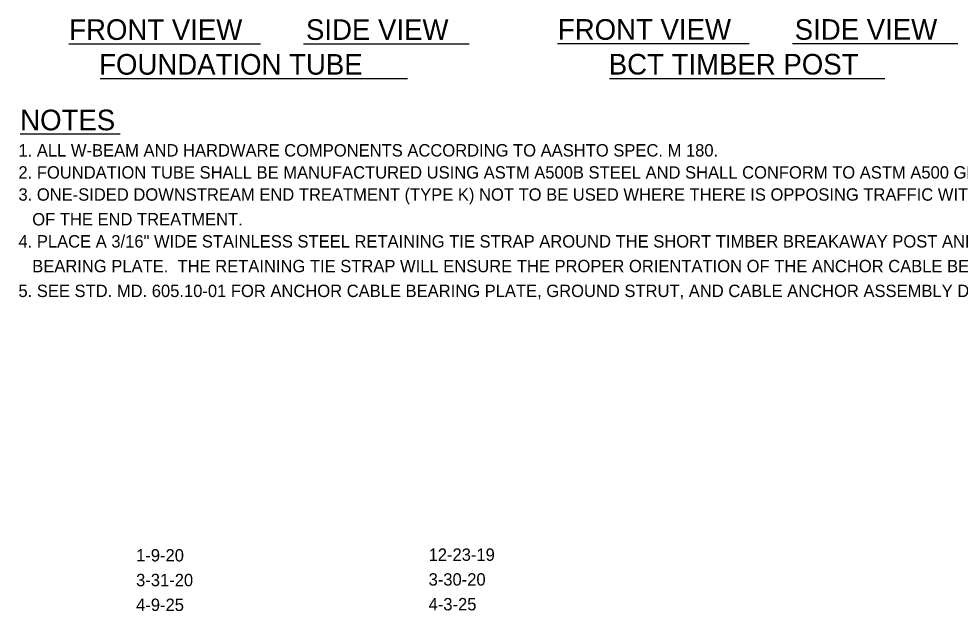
# Model space of a CAD drawing. Extents: x 12.2 to 54.5, y -7.8 to 16.1.
# Drawn here: x 12.398 to 16.963, y 6.013 to 8.884 of the extents above; entities that cross this region are included whole.
import ezdxf

# ---------------------------------------------------------------- set-up
doc = ezdxf.new("R2010")
doc.units = 0
for name, color, linetype in [('DETL-NOTE', 7, 'Continuous'), ('DETL-TITL', 7, 'Continuous'), ('TTLB-TEXT', 7, 'Continuous')]:
    doc.layers.add(name, color=color, linetype=linetype)

msp = doc.modelspace()

# ---------------------------------------------------------------- linework, layer by layer
at = {"layer": 'DETL-NOTE'}
msp.add_line((12.405, 8.3263), (12.8896, 8.3263), dxfattribs=at)
at = {"layer": 'DETL-TITL'}
for p, q in [((15.0111, 8.7636), (15.9397, 8.7636)), ((16.1491, 8.7636), (16.9509, 8.7636)), ((12.6415, 8.763), (13.57, 8.763)), ((13.7794, 8.763), (14.5813, 8.763)), ((12.7928, 8.5945), (14.2825, 8.5945)), ((15.2619, 8.5951), (16.597, 8.5951))]:
    msp.add_line(p, q, dxfattribs=at)

# ---------------------------------------------------------------- texts
at = {"layer": 'DETL-NOTE'}
for s, height, p in [('NOTES', 0.1, (12.405, 8.3434)), ('1. ALL W-BEAM AND HARDWARE COMPONENTS ACCORDING TO AASHTO SPEC. M 180.', 0.06, (12.3966, 8.2163)), ('2. FOUNDATION TUBE SHALL BE MANUFACTURED USING ASTM A500B STEEL AND SHALL CONFORM TO ASTM A500 GRADE B MATERIAL.', 0.06, (12.3966, 8.1093)), ('3. ONE-SIDED DOWNSTREAM END TREATMENT (TYPE K) NOT TO BE USED WHERE THERE IS OPPOSING TRAFFIC WITHIN 30 FT.', 0.06, (12.3966, 8.0022)), ('   OF THE END TREATMENT.', 0.06, (12.3966, 7.8822)), ('4. PLACE A 3/16" WIDE STAINLESS STEEL RETAINING TIE STRAP AROUND THE SHORT TIMBER BREAKAWAY POST AND ANCHOR CABLE', 0.06, (12.3966, 7.7752)), ('   BEARING PLATE.  THE RETAINING TIE STRAP WILL ENSURE THE PROPER ORIENTATION OF THE ANCHOR CABLE BEARING PLATE.', 0.06, (12.3966, 7.6552)), ('5. SEE STD. MD. 605.10-01 FOR ANCHOR CABLE BEARING PLATE, GROUND STRUT, AND CABLE ANCHOR ASSEMBLY DETAILS.', 0.06, (12.3966, 7.5352))]:
    msp.add_text(s, height=height, dxfattribs=at).set_placement(p)
at = {"layer": 'DETL-TITL'}
for s, p in [('FRONT VIEW', (12.6426, 8.7815)), ('SIDE VIEW', (13.7907, 8.7815)), ('FRONT VIEW', (15.0122, 8.7821)), ('SIDE VIEW', (16.1604, 8.7821)), ('FOUNDATION TUBE', (12.7877, 8.613)), ('BCT TIMBER POST', (15.2587, 8.6136))]:
    msp.add_text(s, height=0.1, dxfattribs=at).set_placement(p)
at = {"layer": 'TTLB-TEXT'}
for s, p in [('1-9-20', (12.9671, 6.2537)), ('12-23-19', (14.3853, 6.2567)), ('3-31-20', (12.9671, 6.1337)), ('3-30-20', (14.3853, 6.1367))]:
    msp.add_text(s, height=0.06, rotation=360, dxfattribs=at).set_placement(p)
for s, p in [('4-9-25', (12.9671, 6.0137)), ('4-3-25', (14.3853, 6.0167))]:
    msp.add_text(s, height=0.06, dxfattribs=at).set_placement(p)

doc.saveas('drawing.dxf')
